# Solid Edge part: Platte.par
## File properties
Author: bmolnar
Last saved by: bmolnar
Revision: 77
Sűrűség: 0,000 kg/m^3
Pontosság: 0,990
Username: bmolnar
Dokumentum tartalom típus: 0
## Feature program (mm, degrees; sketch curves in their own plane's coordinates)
base feature "unnamed BaseFeature 1"
thread "unnamed Thread 1"
thread "unnamed Thread 2"
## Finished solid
Body 1: solid body, 65 faces, 114 edges, 62 vertices.
  Faces by surface: plane 38, cylinder 12, cone 10, torus 5
  Edges by curve: line 60, circle 36, spline 18
Bounding box of the edges (mm; curved faces can reach further): 134.000 x 50.000 x 14.000, from (-67, -25, -7.5) to (67, 25, 6.5).
Cylindrical faces by radius (mm): R2.5 x2, R2.75 x2, R3.3235 x2, R4.25 x2, R5 x2, R8 x1, R14 x1
Conical faces (half-angle, radius in mm at the cone's reference point): 45 deg R2.85 x2, 45 deg R3.8235 x4, 45 deg R14.25 x1, 60 deg R1 x2, 60 deg R2.0207 x1
Toroidal faces (ring radius, tube radius in mm): R2.6 r0.1 x2, R3.75 r0.5 x2, R7 r1 x1
Planar faces by outward normal: +x 1, +y 4, +z 7, -x 1, -y 4, -z 5, oblique 16
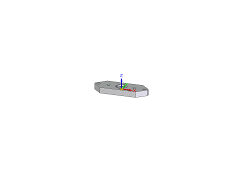
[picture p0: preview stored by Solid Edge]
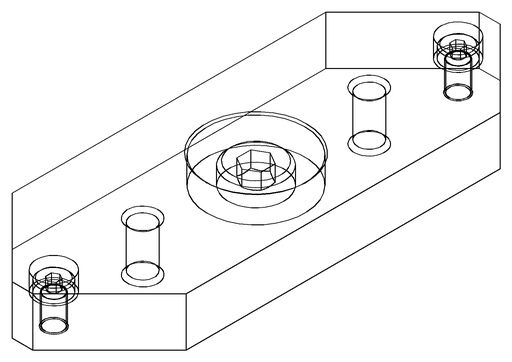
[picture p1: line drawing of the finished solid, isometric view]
